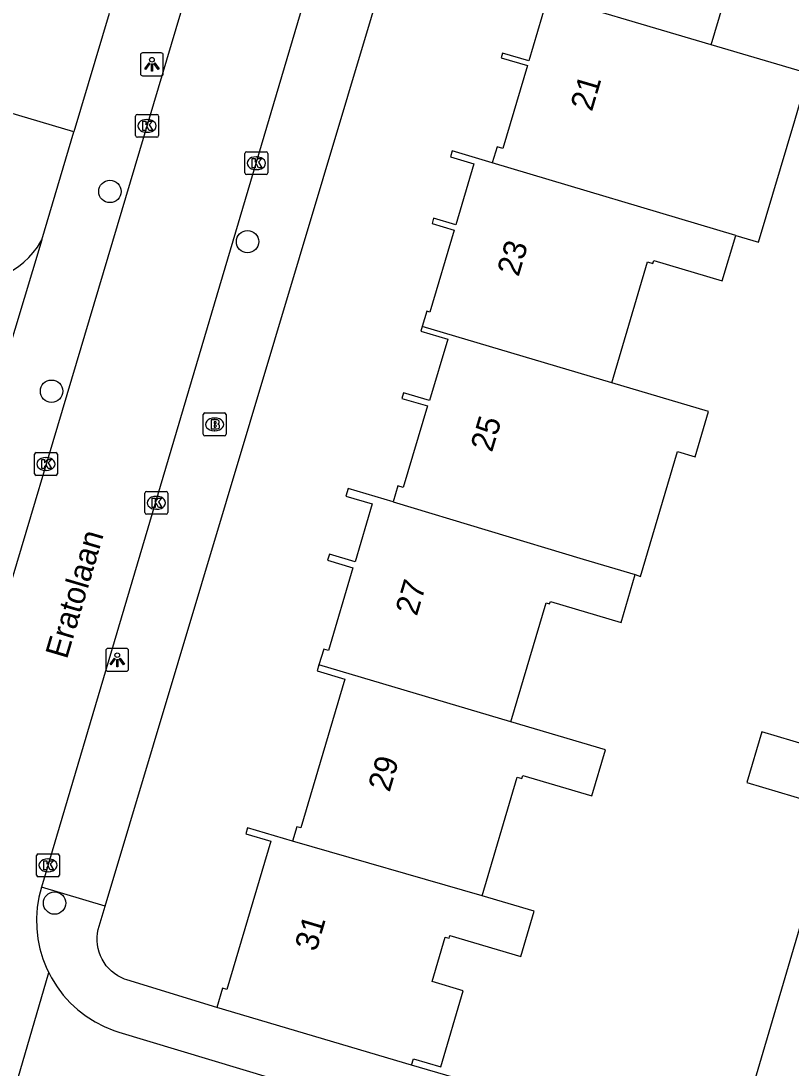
# Model space of a CAD drawing. Extents: x 162186 to 163152, y 385513 to 386513.
# Drawn here: x 162671.49 to 162705.16, y 386036.96 to 386082.74 of the extents above; entities that cross this region are included whole.
import ezdxf

# ---------------------------------------------------------------- set-up
doc = ezdxf.new("R2010")
doc.units = 0
for name, color, linetype in [('IMGEO_Boom', 7, 'Continuous'), ('IMGEO_Brandkraan', 7, 'Continuous'), ('IMGEO_Kolk', 7, 'Continuous'), ('IMGEO_Lichtpunt', 7, 'Continuous'), ('IMGEO_Openbare_ruimte_label', 7, 'Continuous'), ('IMGEO_Pand', 7, 'Continuous'), ('IMGEO_Pand_nummerreeks', 7, 'Continuous'), ('IMGEO_Rijbaan_lokaal_open', 7, 'Continuous'), ('IMGEO_Voetpad_open', 7, 'Continuous')]:
    doc.layers.add(name, color=color, linetype=linetype)

msp = doc.modelspace()

# ---------------------------------------------------------------- linework, layer by layer
at = {"layer": 'IMGEO_Boom'}
for centre in [(162675.38, 386075.286), (162681.398, 386073.091), (162672.827, 386066.552), (162672.96, 386044.176)]:
    msp.add_circle(centre, 0.489, dxfattribs=at)
at = {"layer": 'IMGEO_Brandkraan'}
for p, q in [((162679.458, 386064.675), (162679.458, 386065.527)), ((162679.533, 386065.601), (162680.385, 386065.601)), ((162680.459, 386065.527), (162680.459, 386064.675)), ((162679.946, 386065.381), (162679.971, 386065.381)), ((162680.385, 386064.601), (162679.533, 386064.601)), ((162679.969, 386064.821), (162679.944, 386064.821))]:
    msp.add_line(p, q, dxfattribs=at)
for points in [[(162679.458, 386064.675), (162679.458, 386065.527)], [(162679.533, 386065.601), (162680.385, 386065.601)], [(162680.459, 386065.527), (162680.459, 386064.675)], [(162679.806, 386065.301), (162679.806, 386064.901), (162680.019, 386064.901)], [(162680.037, 386065.301), (162679.806, 386065.301)], [(162679.985, 386065.22), (162679.931, 386065.22), (162679.931, 386065.144)], [(162679.931, 386065.144), (162679.984, 386065.144)], [(162679.993, 386065.068), (162679.931, 386065.068), (162679.931, 386064.987)], [(162680.385, 386064.601), (162679.533, 386064.601)], [(162679.931, 386064.987), (162679.993, 386064.987)]]:
    msp.add_lwpolyline(points, dxfattribs=at)
for centre, radius, start, end in [((162679.535, 386065.525), 0.0765, 91.552, 178.448), ((162679.535, 386065.525), 0.0765, 91.552, 178.448), ((162680.383, 386065.525), 0.0765, 1.552, 88.448), ((162680.383, 386065.525), 0.0765, 1.552, 88.448), ((162679.986, 386065.182), 0.0379, 267.8285, 90.9355), ((162679.994, 386065.027), 0.0404, 269.8759, 90.5077), ((162680.041, 386065.156), 0.145, 59.4692, 91.5367), ((162680.066, 386065.203), 0.0922, 285.5137, 58.1501), ((162680.071, 386065.011), 0.105, 301.3115, 78.989), ((162679.535, 386064.677), 0.0765, 181.552, 268.448), ((162679.535, 386064.677), 0.0765, 181.552, 268.448), ((162680.025, 386065.152), 0.251, 268.6676, 293.5347), ((162680.383, 386064.677), 0.0765, 271.552, 358.448), ((162680.383, 386064.677), 0.0765, 271.552, 358.448)]:
    msp.add_arc(centre, radius, start, end, dxfattribs=at)
for centre, major_axis, ratio, start_param, end_param in [((162679.945, 386065.101), (-0.387, 0.002), 0.722429, 4.712389, 7.853982), ((162679.97, 386065.101), (-0.39, 0.002), 0.717154, 1.570796, 4.712389)]:
    msp.add_ellipse(centre, major_axis=major_axis, ratio=ratio, start_param=start_param, end_param=end_param, dxfattribs=at)
at = {"layer": 'IMGEO_Kolk'}
for p, q in [((162676.504, 386077.726), (162676.504, 386078.578)), ((162676.579, 386078.652), (162677.431, 386078.652)), ((162676.992, 386078.432), (162677.017, 386078.432)), ((162677.505, 386078.578), (162677.505, 386077.726)), ((162677.015, 386077.872), (162676.99, 386077.872)), ((162677.431, 386077.652), (162676.579, 386077.652)), ((162681.282, 386076.094), (162681.282, 386076.946)), ((162681.357, 386077.02), (162682.209, 386077.02)), ((162682.283, 386076.946), (162682.283, 386076.094)), ((162681.77, 386076.8), (162681.795, 386076.8)), ((162682.209, 386076.02), (162681.357, 386076.02)), ((162681.793, 386076.24), (162681.768, 386076.24)), ((162672.082, 386062.943), (162672.082, 386063.795)), ((162672.157, 386063.869), (162673.009, 386063.869)), ((162673.083, 386063.795), (162673.083, 386062.943)), ((162672.57, 386063.649), (162672.595, 386063.649)), ((162673.009, 386062.869), (162672.157, 386062.869)), ((162672.593, 386063.089), (162672.568, 386063.089)), ((162676.908, 386061.247), (162676.908, 386062.099)), ((162676.983, 386062.173), (162677.835, 386062.173)), ((162677.396, 386061.953), (162677.421, 386061.953)), ((162677.909, 386062.099), (162677.909, 386061.247)), ((162677.419, 386061.393), (162677.394, 386061.393)), ((162677.835, 386061.173), (162676.983, 386061.173)), ((162672.248, 386046.327), (162673.1, 386046.327)), ((162672.173, 386045.401), (162672.173, 386046.253)), ((162672.661, 386046.107), (162672.686, 386046.107)), ((162673.174, 386046.253), (162673.174, 386045.401)), ((162672.684, 386045.547), (162672.659, 386045.547)), ((162673.1, 386045.327), (162672.248, 386045.327))]:
    msp.add_line(p, q, dxfattribs=at)
for points in [[(162676.504, 386077.726), (162676.504, 386078.578)], [(162676.579, 386078.652), (162677.431, 386078.652)], [(162676.825, 386078.352), (162676.948, 386078.352), (162676.948, 386078.201), (162677.078, 386078.352), (162677.242, 386078.352), (162677.096, 386078.201), (162677.249, 386077.952), (162677.097, 386077.952), (162677.012, 386078.116), (162676.948, 386078.049), (162676.948, 386077.952), (162676.825, 386077.952), (162676.825, 386078.352)], [(162677.505, 386078.578), (162677.505, 386077.726)], [(162677.431, 386077.652), (162676.579, 386077.652)], [(162681.282, 386076.094), (162681.282, 386076.946)], [(162681.357, 386077.02), (162682.209, 386077.02)], [(162682.283, 386076.946), (162682.283, 386076.094)], [(162681.603, 386076.72), (162681.726, 386076.72), (162681.726, 386076.569), (162681.856, 386076.72), (162682.02, 386076.72), (162681.874, 386076.569), (162682.027, 386076.32), (162681.875, 386076.32), (162681.79, 386076.484), (162681.726, 386076.417), (162681.726, 386076.32), (162681.603, 386076.32), (162681.603, 386076.72)], [(162682.209, 386076.02), (162681.357, 386076.02)], [(162672.082, 386062.943), (162672.082, 386063.795)], [(162672.157, 386063.869), (162673.009, 386063.869)], [(162673.083, 386063.795), (162673.083, 386062.943)], [(162672.403, 386063.569), (162672.526, 386063.569), (162672.526, 386063.418), (162672.656, 386063.569), (162672.82, 386063.569), (162672.674, 386063.418), (162672.827, 386063.169), (162672.675, 386063.169), (162672.59, 386063.333), (162672.526, 386063.266), (162672.526, 386063.169), (162672.403, 386063.169), (162672.403, 386063.569)], [(162673.009, 386062.869), (162672.157, 386062.869)], [(162676.908, 386061.247), (162676.908, 386062.099)], [(162676.983, 386062.173), (162677.835, 386062.173)], [(162677.229, 386061.873), (162677.352, 386061.873), (162677.352, 386061.722), (162677.482, 386061.873), (162677.646, 386061.873), (162677.5, 386061.722), (162677.653, 386061.473), (162677.501, 386061.473), (162677.416, 386061.637), (162677.352, 386061.57), (162677.352, 386061.473), (162677.229, 386061.473), (162677.229, 386061.873)], [(162677.909, 386062.099), (162677.909, 386061.247)], [(162677.835, 386061.173), (162676.983, 386061.173)], [(162672.248, 386046.327), (162673.1, 386046.327)], [(162672.173, 386045.401), (162672.173, 386046.253)], [(162672.494, 386046.027), (162672.617, 386046.027), (162672.617, 386045.876), (162672.747, 386046.027), (162672.911, 386046.027), (162672.765, 386045.876), (162672.918, 386045.627), (162672.766, 386045.627), (162672.681, 386045.791), (162672.617, 386045.724), (162672.617, 386045.627), (162672.494, 386045.627), (162672.494, 386046.027)], [(162673.174, 386046.253), (162673.174, 386045.401)], [(162673.1, 386045.327), (162672.248, 386045.327)]]:
    msp.add_lwpolyline(points, dxfattribs=at)
for centre, start, end in [((162676.581, 386078.576), 91.552, 178.448), ((162676.581, 386078.576), 91.552, 178.448), ((162677.429, 386078.576), 1.552, 88.448), ((162677.429, 386078.576), 1.552, 88.448), ((162676.581, 386077.728), 181.552, 268.448), ((162676.581, 386077.728), 181.552, 268.448), ((162677.429, 386077.728), 271.552, 358.448), ((162677.429, 386077.728), 271.552, 358.448), ((162681.359, 386076.944), 91.552, 178.448), ((162681.359, 386076.944), 91.552, 178.448), ((162682.207, 386076.944), 1.552, 88.448), ((162682.207, 386076.944), 1.552, 88.448), ((162681.359, 386076.096), 181.552, 268.448), ((162681.359, 386076.096), 181.552, 268.448), ((162682.207, 386076.096), 271.552, 358.448), ((162682.207, 386076.096), 271.552, 358.448), ((162672.159, 386063.793), 91.552, 178.448), ((162672.159, 386063.793), 91.552, 178.448), ((162673.007, 386063.793), 1.552, 88.448), ((162673.007, 386063.793), 1.552, 88.448), ((162672.159, 386062.945), 181.552, 268.448), ((162672.159, 386062.945), 181.552, 268.448), ((162673.007, 386062.945), 271.552, 358.448), ((162673.007, 386062.945), 271.552, 358.448), ((162676.985, 386062.097), 91.552, 178.448), ((162676.985, 386062.097), 91.552, 178.448), ((162677.833, 386062.097), 1.552, 88.448), ((162677.833, 386062.097), 1.552, 88.448), ((162676.985, 386061.249), 181.552, 268.448), ((162676.985, 386061.249), 181.552, 268.448), ((162677.833, 386061.249), 271.552, 358.448), ((162677.833, 386061.249), 271.552, 358.448), ((162672.25, 386046.251), 91.552, 178.448), ((162672.25, 386046.251), 91.552, 178.448), ((162673.098, 386046.251), 1.552, 88.448), ((162673.098, 386046.251), 1.552, 88.448), ((162672.25, 386045.403), 181.552, 268.448), ((162672.25, 386045.403), 181.552, 268.448), ((162673.098, 386045.403), 271.552, 358.448), ((162673.098, 386045.403), 271.552, 358.448)]:
    msp.add_arc(centre, 0.0765, start, end, dxfattribs=at)
for centre, major_axis, ratio, start_param, end_param in [((162676.991, 386078.152), (-0.387, 0.002), 0.722429, 4.712389, 7.853982), ((162677.016, 386078.152), (-0.39, 0.002), 0.717154, 1.570796, 4.712389), ((162681.769, 386076.52), (-0.387, 0.002), 0.722429, 4.712389, 7.853982), ((162681.794, 386076.52), (-0.39, 0.002), 0.717154, 1.570796, 4.712389), ((162672.569, 386063.369), (-0.387, 0.002), 0.722429, 4.712389, 7.853982), ((162672.594, 386063.369), (-0.39, 0.002), 0.717154, 1.570796, 4.712389), ((162677.395, 386061.673), (-0.387, 0.002), 0.722429, 4.712389, 7.853982), ((162677.42, 386061.673), (-0.39, 0.002), 0.717154, 1.570796, 4.712389), ((162672.66, 386045.827), (-0.387, 0.002), 0.722429, 4.712389, 7.853982), ((162672.685, 386045.827), (-0.39, 0.002), 0.717154, 1.570796, 4.712389)]:
    msp.add_ellipse(centre, major_axis=major_axis, ratio=ratio, start_param=start_param, end_param=end_param, dxfattribs=at)
at = {"layer": 'IMGEO_Lichtpunt'}
for p, q in [((162676.717, 386081.245), (162676.717, 386080.438)), ((162676.717, 386081.245), (162676.717, 386080.438)), ((162677.619, 386081.34), (162676.811, 386081.34)), ((162677.619, 386081.34), (162676.811, 386081.34)), ((162677.713, 386080.438), (162677.713, 386081.245)), ((162677.713, 386080.438), (162677.713, 386081.245)), ((162676.811, 386080.344), (162677.619, 386080.344)), ((162676.811, 386080.344), (162677.619, 386080.344)), ((162675.201, 386055.213), (162675.201, 386054.406)), ((162675.201, 386055.213), (162675.201, 386054.406)), ((162676.103, 386055.308), (162675.295, 386055.308)), ((162676.103, 386055.308), (162675.295, 386055.308)), ((162676.197, 386054.406), (162676.197, 386055.213)), ((162676.197, 386054.406), (162676.197, 386055.213)), ((162675.295, 386054.312), (162676.103, 386054.312)), ((162675.295, 386054.312), (162676.103, 386054.312))]:
    msp.add_line(p, q, dxfattribs=at)
for points in [[(162677.091, 386080.909), (162677.13, 386080.881), (162676.942, 386080.619), (162676.904, 386080.646), (162677.091, 386080.909)], [(162677.193, 386080.861), (162677.24, 386080.861), (162677.24, 386080.539), (162677.193, 386080.539), (162677.193, 386080.861)], [(162677.303, 386080.881), (162677.341, 386080.908), (162677.528, 386080.646), (162677.489, 386080.618), (162677.303, 386080.881)], [(162675.575, 386054.877), (162675.614, 386054.849), (162675.426, 386054.587), (162675.388, 386054.614), (162675.575, 386054.877)], [(162675.677, 386054.829), (162675.724, 386054.829), (162675.724, 386054.507), (162675.677, 386054.507), (162675.677, 386054.829)], [(162675.787, 386054.849), (162675.825, 386054.876), (162676.012, 386054.614), (162675.973, 386054.586), (162675.787, 386054.849)]]:
    msp.add_lwpolyline(points, dxfattribs=at)
for centre in [(162677.216, 386081.043), (162675.7, 386055.011)]:
    msp.add_circle(centre, 0.0994, dxfattribs=at)
for centre, start, end in [((162676.811, 386081.245), 90, 180), ((162676.811, 386081.245), 90, 180), ((162677.619, 386081.245), 0, 90), ((162677.619, 386081.245), 0, 90), ((162676.811, 386080.438), 180, 270), ((162676.811, 386080.438), 180, 270), ((162677.619, 386080.438), 270, 0), ((162677.619, 386080.438), 270, 360), ((162675.295, 386055.213), 90, 180), ((162675.295, 386055.213), 90, 180), ((162676.103, 386055.213), 0, 90), ((162676.103, 386055.213), 0, 90), ((162675.295, 386054.406), 180, 270), ((162675.295, 386054.406), 180, 270), ((162676.103, 386054.406), 270, 0), ((162676.103, 386054.406), 270, 360)]:
    msp.add_arc(centre, 0.0946, start, end, dxfattribs=at)
at = {"layer": 'IMGEO_Pand'}
for points in [[(162701.668, 386081.701), (162703.238, 386086.998), (162703.409, 386086.947), (162703.45, 386087.085), (162706.527, 386086.173), (162708.135, 386085.696), (162708.688, 386087.783)], [(162673.803, 386077.892), (162663.627, 386080.915), (162664.371, 386083.421), (162664.111, 386083.498), (162664.378, 386084.395), (162664.205, 386084.446)], [(162693.378, 386084.153), (162693.306, 386083.908), (162694.455, 386083.567), (162693.693, 386080.996), (162692.549, 386081.335), (162692.489, 386081.131), (162693.638, 386080.791), (162692.562, 386077.157), (162692.304, 386077.233), (162692.099, 386076.541)], [(162701.668, 386081.701), (162693.378, 386084.153)], [(162675.341, 386083.069), (162673.803, 386077.892)], [(162702.738, 386073.361), (162703.743, 386073.063), (162705.32, 386078.384), (162705.929, 386080.439), (162701.668, 386081.701)], [(162692.099, 386076.541), (162690.343, 386077.061), (162690.267, 386076.802), (162691.297, 386076.497), (162690.507, 386073.831), (162689.534, 386074.119), (162689.464, 386073.883), (162690.433, 386073.596), (162689.371, 386070.009), (162689.23, 386070.051), (162689.031, 386069.378)], [(162702.738, 386073.361), (162692.099, 386076.541)], [(162697.324, 386066.925), (162698.888, 386072.204), (162699.116, 386072.137), (162699.155, 386072.267), (162702.151, 386071.379), (162702.738, 386073.361)], [(162689.031, 386069.378), (162688.971, 386069.176), (162690.148, 386068.827), (162689.354, 386066.146), (162688.215, 386066.484), (162688.142, 386066.239), (162689.26, 386065.907), (162688.204, 386062.34), (162687.972, 386062.409), (162687.766, 386061.712)], [(162697.324, 386066.925), (162689.031, 386069.378)], [(162698.343, 386058.534), (162698.58, 386058.449), (162700.2, 386063.917), (162700.969, 386063.689), (162701.556, 386065.67), (162697.324, 386066.925)], [(162687.766, 386061.712), (162685.795, 386062.296), (162685.698, 386061.968), (162686.847, 386061.627), (162686.097, 386059.096), (162684.978, 386059.427), (162684.899, 386059.16), (162686.004, 386058.833), (162684.932, 386055.214), (162684.725, 386055.275), (162684.52, 386054.583)], [(162687.766, 386061.712), (162696.076, 386059.205), (162698.343, 386058.534)], [(162692.913, 386052.101), (162694.452, 386057.297), (162694.604, 386057.252), (162694.636, 386057.362), (162697.725, 386056.447), (162698.343, 386058.534)], [(162684.52, 386054.583), (162684.445, 386054.328), (162685.656, 386053.97), (162683.728, 386047.462), (162683.55, 386047.515), (162683.361, 386046.876)], [(162692.913, 386052.101), (162684.52, 386054.583)], [(162691.648, 386044.491), (162693.186, 386049.681), (162693.392, 386049.62), (162693.431, 386049.753), (162696.455, 386048.857), (162697.052, 386050.873), (162692.913, 386052.101)], [(162703.22, 386049.445), (162706.649, 386048.429), (162707.304, 386050.641), (162703.875, 386051.656), (162703.22, 386049.445)], [(162683.361, 386046.876), (162681.4, 386047.457), (162681.324, 386047.203), (162682.417, 386046.879), (162680.496, 386040.392), (162680.3, 386040.45), (162680.051, 386039.612)], [(162691.648, 386044.491), (162683.361, 386046.876)], [(162688.571, 386037.088), (162688.652, 386037.364), (162689.841, 386037.012), (162690.827, 386040.343), (162689.465, 386040.746), (162690.039, 386042.685), (162690.208, 386042.636), (162690.245, 386042.762), (162693.342, 386041.845), (162693.926, 386043.816), (162691.648, 386044.491)], [(162688.571, 386037.088), (162680.051, 386039.612)]]:
    msp.add_lwpolyline(points, dxfattribs=at)
at = {"layer": 'IMGEO_Rijbaan_lokaal_open'}
for points in [[(162662.333, 386028.923), (162682.265, 386095.831)], [(162682.265, 386095.831), (162687.061, 386094.431), (162672.384, 386044.868)], [(162672.384, 386044.868), (162672.273, 386044.426), (162672.201, 386043.976), (162672.17, 386043.522), (162672.18, 386043.066), (162672.23, 386042.613), (162672.321, 386042.167), (162672.451, 386041.73), (162672.62, 386041.307), (162672.704, 386041.141)], [(162684.772, 386029.534), (162670.528, 386033.7), (162672.704, 386041.141)]]:
    msp.add_lwpolyline(points, dxfattribs=at)
at = {"layer": 'IMGEO_Voetpad_open'}
for points in [[(162675.165, 386044.035), (162690.004, 386093.566), (162693.881, 386106.506)], [(162613.841, 386087.903), (162652.771, 386076.351), (162668.548, 386071.532), (162668.837, 386071.463), (162669.13, 386071.419), (162669.426, 386071.403), (162669.723, 386071.412), (162670.017, 386071.449), (162670.308, 386071.511), (162670.591, 386071.599), (162670.865, 386071.712), (162671.128, 386071.849), (162671.378, 386072.009), (162671.613, 386072.19), (162671.83, 386072.392), (162672.029, 386072.613), (162672.207, 386072.85), (162672.363, 386073.102), (162672.402, 386073.174)], [(162672.402, 386073.174), (162673.803, 386077.892)], [(162672.402, 386073.174), (162670.024, 386065.332)], [(162711.228, 386062.433), (162703.157, 386035.017)], [(162675.165, 386044.035), (162672.384, 386044.868)], [(162680.051, 386039.612), (162676.122, 386040.818), (162676.023, 386040.852), (162675.869, 386040.919), (162675.722, 386040.999), (162675.582, 386041.091), (162675.451, 386041.196), (162675.331, 386041.312), (162675.221, 386041.438), (162675.122, 386041.574), (162675.037, 386041.718), (162674.964, 386041.869), (162674.905, 386042.026), (162674.861, 386042.187), (162674.831, 386042.352), (162674.816, 386042.519), (162674.815, 386042.686), (162674.83, 386042.853), (162674.86, 386043.018), (162675.165, 386044.035)], [(162672.704, 386041.141), (162672.826, 386040.9), (162673.067, 386040.513), (162673.342, 386040.15), (162673.648, 386039.813), (162673.983, 386039.504), (162674.344, 386039.226), (162674.729, 386038.982), (162675.134, 386038.773), (162675.556, 386038.602), (162675.766, 386038.532), (162686.463, 386035.313)], [(162700.828, 386033.514), (162688.571, 386037.088)]]:
    msp.add_lwpolyline(points, dxfattribs=at)

# ---------------------------------------------------------------- texts
at = {"layer": 'IMGEO_Openbare_ruimte_label'}
msp.add_text('Eratolaan', height=1, rotation=73.5587, dxfattribs=at).set_placement((162673.498, 386054.804))
at = {"layer": 'IMGEO_Pand_nummerreeks'}
for s, rotation, p in [('21', 73.5471, (162696.452, 386078.749)), ('23', 73.4662, (162693.243, 386071.527)), ('25', 73.3157, (162692.081, 386063.85)), ('27', 73.3737, (162688.795, 386056.69)), ('29', 73.498, (162687.603, 386048.992)), ('31', 73.5048, (162684.399, 386042.02))]:
    msp.add_text(s, height=1, rotation=rotation, dxfattribs=at).set_placement(p)

doc.saveas('drawing.dxf')
